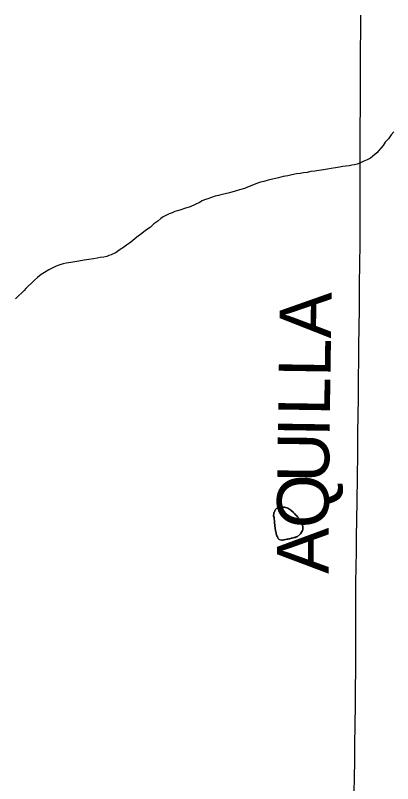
# Model space of a CAD drawing. Extents: x 103424 to 290657, y 38711 to 110967.
# Drawn here: x 149781 to 151982, y 76839 to 81314 of the extents above; entities that cross this region are included whole.
import ezdxf

# ---------------------------------------------------------------- set-up
doc = ezdxf.new("R2010")
doc.units = 0
for name, color, linetype in [('GM_X_County_Road', 7, 'Continuous'), ('GM_X_County_Road_Text', 7, 'Continuous'), ('GM_X_Minor_Lake', 7, 'Continuous'), ('GM_X_Minor_River', 7, 'Continuous')]:
    doc.layers.add(name, color=color, linetype=linetype)

msp = doc.modelspace()

# ---------------------------------------------------------------- linework, layer by layer
at = {"layer": 'GM_X_County_Road'}
msp.add_lwpolyline([(151757.5, 76788.4), (151759.5, 76875.1), (151760.8, 76970.2), (151762, 77065.4), (151763.1, 77180.4), (151764.2, 77295.4), (151765.2, 77396.1), (151766.1, 77496.9), (151766.9, 77608.8), (151767.6, 77720.8), (151767.1, 77815.9), (151766.6, 77911), (151767.6, 78007.6), (151768.7, 78104.3), (151770.2, 78188.4), (151771.7, 78272.6), (151773.2, 78378.7), (151774.3, 78478.6), (151776.3, 78630.1), (151777.9, 78755.1), (151779.6, 78880), (151781, 78982.8), (151782.4, 79085.6), (151783.4, 79198.3), (151784.5, 79311), (151785.2, 79399), (151786, 79487), (151787.5, 79617.3), (151789.1, 79747.6), (151790.3, 79864.4), (151791.6, 79981.2), (151792.6, 80350.9), (151793, 80482.5), (151794.1, 80958.1), (151794.5, 81042), (151795, 81127.4), (151795.4, 81212.9), (151796.3, 81315.9)], dxfattribs=at)
at = {"layer": 'GM_X_Minor_Lake'}
for points in [[(151326, 78449.4), (151344.2, 78449.5), (151350.3, 78449.5), (151356.3, 78447.5), (151364.4, 78445.5), (151370.5, 78443.5), (151388.7, 78431.5), (151402.8, 78417.4), (151408.9, 78413.4), (151415, 78405.3), (151421, 78401.3), (151427.1, 78393.2), (151433.2, 78387.2), (151437.2, 78379.1), (151443.3, 78373.1), (151445.3, 78367), (151449.4, 78361), (151457.5, 78336.8), (151457.6, 78318.6), (151455.6, 78312.5), (151443.5, 78294.3), (151425.4, 78276.1), (151419.3, 78276.1), (151413.3, 78272), (151407.2, 78272), (151395.1, 78267.9), (151389.1, 78267.9), (151383, 78265.8), (151377, 78265.8), (151370.9, 78263.8), (151364.9, 78263.8), (151356.8, 78261.7), (151350.8, 78259.7), (151344.7, 78259.7), (151338.7, 78257.6), (151332.6, 78257.6), (151320.5, 78261.6), (151314.4, 78267.6), (151310.4, 78275.7), (151306.3, 78281.7), (151302.2, 78293.8), (151302.2, 78299.9), (151298.1, 78312), (151298.1, 78318.1), (151296.1, 78324.1), (151296.1, 78330.2), (151294, 78336.2), (151294, 78348.3), (151292, 78354.4), (151291.9, 78372.6), (151289.9, 78378.6), (151289.9, 78390.7), (151287.8, 78396.8), (151287.8, 78402.8), (151289.8, 78408.9), (151289.8, 78415), (151293.8, 78427.1), (151297.8, 78435.2), (151303.9, 78441.3), (151313.9, 78445.3), (151326, 78449.4)], [(151326, 78449.4), (151313.9, 78445.3), (151303.9, 78441.3), (151297.8, 78435.2), (151293.8, 78427.1), (151289.8, 78415), (151289.8, 78408.9), (151287.8, 78402.8), (151287.8, 78396.8), (151289.9, 78390.7), (151289.9, 78378.6), (151291.9, 78372.6), (151292, 78354.4), (151294, 78348.3), (151294, 78336.2), (151296.1, 78330.2), (151296.1, 78324.1), (151298.1, 78318.1), (151298.1, 78312), (151302.2, 78299.9), (151302.2, 78293.8), (151306.3, 78281.7), (151310.4, 78275.7), (151314.4, 78267.6), (151320.5, 78261.6), (151332.6, 78257.6), (151338.7, 78257.6), (151344.7, 78259.7), (151350.8, 78259.7), (151356.8, 78261.7), (151364.9, 78263.8)], [(151364.9, 78263.8), (151370.9, 78263.8), (151377, 78265.8), (151383, 78265.8), (151389.1, 78267.9), (151395.1, 78267.9), (151407.2, 78272), (151413.3, 78272), (151419.3, 78276.1), (151425.4, 78276.1), (151443.5, 78294.3), (151455.6, 78312.5), (151457.6, 78318.6), (151457.5, 78336.8), (151449.4, 78361), (151445.3, 78367), (151443.3, 78373.1), (151437.2, 78379.1), (151433.2, 78387.2), (151427.1, 78393.2), (151421, 78401.3), (151415, 78405.3), (151408.9, 78413.4), (151402.8, 78417.4), (151388.7, 78431.5), (151370.5, 78443.5), (151364.4, 78445.5), (151356.3, 78447.5), (151350.3, 78449.5), (151344.2, 78449.5), (151326, 78449.4)]]:
    msp.add_lwpolyline(points, dxfattribs=at)
at = {"layer": 'GM_X_Minor_River'}
for points in [[(151988.8, 80635.4), (151972.9, 80618.9), (151957.2, 80594.4), (151937.4, 80575.9), (151925.6, 80555.4), (151890.1, 80514.4), (151878.2, 80504.1), (151866.2, 80493.8), (151852.3, 80483.4), (151832.3, 80473), (151814.3, 80464.6), (151790.3, 80454), (151774.2, 80447.7), (151760.2, 80443.4), (151744.1, 80441.1), (151728, 80438.8), (151709.9, 80436.4), (151691.8, 80434.1), (151671.7, 80429.7), (151647.5, 80427.2), (151623.4, 80422.7), (151601.2, 80418.3), (151579.1, 80413.9), (151550.9, 80411.3), (151528.8, 80406.9), (151504.6, 80404.5), (151482.5, 80400), (151462.4, 80397.6), (151442.3, 80393.2), (151420.1, 80390.8), (151394, 80386.3), (151369.9, 80379.8), (151343.7, 80375.3), (151315.6, 80368.7), (151281.5, 80360), (151255.3, 80353.5), (151231.2, 80347), (151211.2, 80342.6), (151193.1, 80336.2), (151171.1, 80327.8), (151145, 80317.2), (151117, 80306.6), (151088.9, 80298), (151062.8, 80289.4), (151030.7, 80280.8), (151004.6, 80274.3), (150980.4, 80269.8), (150966.4, 80265.5), (150946.3, 80261.1), (150926.2, 80252.6), (150904.2, 80246.2), (150884.1, 80239.8), (150870.1, 80233.4), (150856.1, 80225.1), (150800.1, 80199.9), (150768, 80189.2), (150745.9, 80180.7), (150727.9, 80176.4), (150711.8, 80172), (150695.8, 80163.7), (150677.8, 80157.3), (150659.7, 80148.9), (150643.8, 80140.5), (150629.8, 80130.1), (150611.9, 80115.7), (150590, 80099.1)], [(150590, 80099.1), (150568.2, 80078.5), (150540.2, 80061.9), (150518.4, 80043.3), (150498.5, 80028.8), (150480.6, 80014.3), (150464.6, 80001.9), (150446.7, 79987.5), (150428.8, 79975), (150414.9, 79964.7), (150402.9, 79956.4), (150387, 79946), (150369, 79933.5), (150341, 79918.9), (150327, 79914.6), (150314.9, 79910.4), (150296.9, 79906), (150276.7, 79903.6), (150258.7, 79899.2), (150236.5, 79896.8), (150210.4, 79892.3), (150182.2, 79887.8), (150152, 79883.2), (150127.9, 79878.7), (150105.8, 79874.3), (150077.6, 79871.7), (150059.5, 79867.4), (150041.4, 79861), (150019.4, 79852.5), (149999.4, 79844.1), (149977.4, 79831.6), (149951.4, 79816.9), (149931.5, 79804.5), (149911.6, 79787.9), (149893.7, 79771.5), (149875.9, 79755), (149856, 79736.4), (149842.1, 79724.1), (149832.2, 79711.8), (149788.6, 79668.6), (149781.5, 79662.2)]]:
    msp.add_lwpolyline(points, dxfattribs=at)

# ---------------------------------------------------------------- texts
at = {"layer": 'GM_X_County_Road_Text'}
for s, rotation, p in [('A', 89.1366, (151622.3, 79432.2)), ('L', 89.1386, (151618.9, 79206.4)), ('L', 89.1416, (151615.5, 78980.6)), ('I', 89.1335, (151613.7, 78856.7)), ('U', 89.2933, (151610.4, 78591.3)), ('Q', 89.6721, (151608.9, 78326.1)), ('A', 89.9672, (151608.7, 78060.9))]:
    msp.add_text(s, height=301.9, rotation=rotation, dxfattribs=at).set_placement(p)

doc.saveas('drawing.dxf')
